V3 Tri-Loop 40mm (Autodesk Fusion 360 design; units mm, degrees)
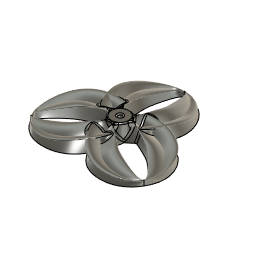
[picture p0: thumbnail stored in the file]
work_plane "WorkPlane9" AlongDistance 2
work_plane "WorkPlane10" AlongDistance -2
coil_primitive "CoilPrimitive4" Diameter 12 SectionSize 1 TaperAngle 0 Height 38.1 (= "( 25.4 * 1.5 ) * 1 mm")
coil_primitive "CoilPrimitive5" Diameter 25.4 SectionSize 1 TaperAngle 0 Height 38.1 (= "( 25.4 * 1.5 ) * 1 mm")
move "Move1"
sketch "Profile Start" plane through (2, 0, 0) normal (1, 0, 0) x axis (0, 1, 0)
  line L1 (-1.4, 0) -> (-2, 0)
  curve K1 (-2, 0) -> (-1.4, 0)
  curve K2 (-3, -1.5) -> (-1, 1.5)
  curve K3 (-0.4, 1.5) -> (-2.4, -1.5)
  curve K4 (1.75, 5) -> (2.25, 5)
  point P2 (-2, 0)
  point P4 (-1.4, 0)
  point P3 (2, 5)
  point P1 (0, 0)
  point P5 (-1, 1.5)
  point P8 (-0.4, 1.5)
  point P9 (2.25, 5)
  point P10 (1.75, 5)
  horizontal L1
  midpoint P2 K2
  midpoint P4 K3
  midpoint P3 K4
  dimension "d65" distance P1 P3 = 2
  dimension "d66" distance P1 P3 = 5
  dimension "d67" distance P1 P2 = 2
  dimension "d68" distance P2 P5 = 1
  dimension "d69" distance P2 P5 = 1.5
  dimension "d70" distance P4 P8 = 1.5
  dimension "d71" distance P5 P8 = 0.6
  dimension "d72" distance P9 P10 = 0.5
  dimension "d134" distance P2 P4 = 0.6
sketch "Profile End" plane through (-2, 0, 0) normal (1, 0, 0) x axis (0, 1, 0)
  curve K1 (3, 0) -> (2.2, 0)
  curve K2 (1.5, 1.5) -> (3.3167, -1.2219)
  curve K3 (-1.75, 4.2501) -> (-2.25, 4.2501)
  curve K4 (4, -1.5) -> (2, 1.5)
  line L1 (-1.75, 4.2501) -> (-2.25, 4.2501)
  line L2 (2.2, 0) -> (3, 0)
  point P5 (-1.75, 4.2501)
  point P9 (-2.25, 4.2501)
  point P4 (2.2, 0)
  point P8 (3, 0)
  point P6 (-2, 4.25)
  point P11 (0, 0)
  point P3 (1.5, 1.5)
  point P7 (2, 1.5)
  dimension "d84" distance P5 P9 = 0.5
  dimension "d89" distance P4 P8 = 0.8
  dimension "d101" distance P6 P11 = 4.25
  dimension "d102" distance P6 P11 = 2
  dimension "d103" distance P8 P11 = 3
  dimension "d104" distance P3 P11 = 1.5
  dimension "d105" distance P3 P11 = 1.5
  dimension "d106" distance P7 P11 = 2
  dimension "d107" distance P7 P11 = 1.5
sketch "Target Shape" plane through (0, 0, 0) normal (0, 0, 1) x axis (1, 0, 0)
  circle C1 centre (0, 0) radius 25.4
  circle C2 centre (0, 11.7) radius 13.7
  point P1 (0, 0)
  point P2 (0, 0)
  coincident P1 P2
  tangent C1 C2
  dimension "d95" diameter C1 = 50.8
sketch "Profile Edge" plane through (0, 0, 0) normal (1, 0, 0) x axis (0, 1, 0)
  line L1 (20, 0) -> (19.6, 0)
  curve K1 (19.6, 0) -> (20, 0)
  curve K2 (19.7001, 1.4961) -> (19.8999, 1.5039)
  curve K3 (20, 0.8) -> (20, -0.8)
  curve K4 (19.6, -0.8) -> (19.6, 0.8)
  point P4 (19.8, 1.5)
  point P3 (20, 0)
  point P2 (19.6, 0)
  point P1 (0, 0)
  point P5 (19.8999, 1.5039)
  point P6 (19.7001, 1.4961)
  horizontal L1
  midpoint P4 K2
  midpoint P3 K3
  midpoint P2 K4
  dimension "d96" distance P2 P3 = 0.4
  dimension "d98" distance P3 P4 = 1.5
  dimension "d121" distance P1 P4 = 1.5
  dimension "d138" distance P5 P6 = 0.2
  dimension "d196" distance P1 P3 = 20
  dimension "d209" distance P3 P4 = 0.2
work_plane "WorkPlane11" AlongDistance 10
sketch "Profile Mid" plane through (0, 10, 0) normal (0, 1, 0) x axis (1, 0, 0)
  line L1 (9.3, 0) -> (10, 0)
  curve K1 (9.3, 0) -> (10, 0)
  curve K2 (2.8905, -3.3974) -> (3.1095, -3.6026)
  curve K3 (11, 1.5) -> (7.6, -1.5)
  curve K4 (8.3, -1.5) -> (11.7, 1.5)
  line L2 (-3.7, 0) -> (-3, 0)
  curve K5 (-3.7, 0) -> (-3, 0)
  curve K6 (-4.915, -1.3314) -> (-1.085, 1.3314)
  curve K7 (-10.1189, -3.4086) -> (-9.8811, -3.5914)
  curve K8 (-1.5, 1.5) -> (-5.9, -1.5)
  point P3 (3, -3.5)
  point P4 (9.3, 0)
  point P2 (10, 0)
  point P15 (-10, -3.5)
  point P14 (-3.7, 0)
  point P11 (-3, 0)
  point P5 (3.1095, -3.6026)
  point P6 (2.8905, -3.3974)
  point P1 (0, 0)
  point P18 (-10.1189, -3.4086)
  point P19 (-9.8811, -3.5914)
  midpoint P3 K2
  midpoint P4 K3
  midpoint P2 K4
  midpoint P15 K7
  midpoint P14 K8
  midpoint P11 K6
  dimension "d109" distance P2 P4 = 0.7
  dimension "d110" distance P2 P3 = 3.5
  dimension "d111" distance P2 P3 = 7
  dimension "d112" distance P5 P6 = 0.3
  dimension "d113" distance P1 P2 = 10
  dimension "d117" distance P18 P19 = 0.3
  dimension "d118" distance P1 P15 = 10
  dimension "d187" distance P1 P15 = 3.5
  dimension "d197" distance P11 P14 = 0.7
  dimension "d198" distance P11 P15 = 7
sketch "Lower Rails" plane through (0, 0, 0) normal (0, 0, 1) x axis (1, 0, 0)
  curve K1 (-2, 2.2) -> (0, 20)
  curve K2 (-0.355, 2.2) -> (-3.645, 2.2)
  curve K3 (-3.9029, 5.1529) -> (-3.4971, 14.8471)
  curve K4 (-1.5, 20) -> (1.5, 20)
  curve K5 (-2, 3) -> (0, 19.6)
  curve K6 (-1.2, 3) -> (-2.8, 3)
  curve K7 (-2.9941, 6.3775) -> (-3.0059, 13.6225)
  curve K8 (-1.25, 19.6) -> (1.25, 19.6)
  curve K9 (0, 20) -> (2, -2)
  curve K10 (-3, 20) -> (3, 20)
  curve K11 (10, 12.7401) -> (10, 7.2599)
  curve K12 (2.5, -2) -> (1.5, -2)
  curve K13 (0, 19.6) -> (2, -1.4)
  curve K14 (-2.9656, 19.6) -> (2.9656, 19.6)
  curve K15 (9.3, 12.3) -> (9.3, 7.7)
  curve K16 (2.5, -1.4) -> (1.5, -1.4)
  circle C1 centre (0, 10) radius 10
  point P6 (-3.7, 10)
  point P9 (-3.7, 10)
  point P7 (-2, 2.2)
  point P10 (-2, 2.2)
  point P8 (0, 20)
  point P18 (-3, 10)
  point P20 (-3, 10)
  point P4 (-2, 3)
  point P19 (-2, 3)
  point P17 (0, 19.6)
  point P27 (0, 20)
  point P1 (0, 0)
  point P29 (2, -2)
  point P31 (2, -2)
  point P28 (10, 10)
  point P32 (10, 10)
  point P39 (2, -1.4)
  point P41 (2, -1.4)
  point P5 (9.3, 10)
  point P40 (9.3, 10)
  point P25 (1.25, 19.6)
  point P26 (-1.25, 19.6)
  point P15 (1.5, 20)
  point P16 (-1.5, 20)
  coincident P6 P9
  coincident P7 P10
  midpoint P10 K2
  midpoint P9 K3
  midpoint P8 K4
  coincident P18 P20
  coincident P4 P19
  midpoint P19 K6
  parallel K2 K6
  midpoint P18 K7
  midpoint P17 K8
  coincident P8 P27
  coincident P8 C1
  coincident P1 C1
  horizontal K4
  coincident P29 P31
  coincident P28 P32
  midpoint P8 K10
  horizontal K10
  midpoint P32 K11
  vertical K11
  midpoint P31 K12
  horizontal K12
  horizontal K6
  coincident P39 P41
  coincident P5 P40
  midpoint P17 K14
  horizontal K14
  midpoint P40 K15
  vertical K15
  midpoint P39 K16
  horizontal K16
  horizontal K8
  dimension "d136" distance P25 P26 = 2.5
  dimension "d137" distance P15 P16 = 3
work_plane "WorkPlane12" AlongDistance 5
sketch "Upper Rails" plane through (0, 0, 5) normal (0, 0, 1) x axis (1, 0, 0)
  line L1 (0, 20) -> (0, 19.6)
  curve K1 (2, 2) -> (0, 19.8)
  curve K2 (1.3, 2) -> (2.7, 2)
  curve K3 (3.01, 7.875) -> (2.9914, 12.125)
  curve K4 (1.5, 19.8) -> (-1.5, 19.8)
  curve K5 (-2, -2) -> (0, 19.8)
  curve K6 (1.5, -2) -> (-5.5, -2)
  curve K7 (-4, 19.8) -> (4, 19.8)
  curve K8 (-10.0007, 5.1189) -> (-10.0007, 14.8811)
  point P7 (2, 2)
  point P9 (2, 2)
  point P6 (3.0007, 10)
  point P5 (0, 19.8)
  point P18 (-2, -2)
  point P16 (0, 19.8)
  point P17 (-10.0007, 10)
  point P14 (-1.5, 19.8)
  point P15 (1.5, 19.8)
  coincident P7 P9
  midpoint P7 K2
  midpoint P6 K3
  midpoint P5 K4
  midpoint P18 K6
  midpoint P16 K7
  midpoint P17 K8
  dimension "d135" distance P14 P15 = 3
loft "Loft3" sketch "Profile Start" + "Profile Mid" + "Profile Edge" bodies "40mmx1x3 CCW"
loft "Loft4" sketch "Profile Edge" + "Profile Mid" + "Profile End"
circular_pattern "C-Pattern2" TotalAngle 360
combine "Combine2" bodies "Blade Template 2x1.6x3 (1)"
circular_pattern "C-Pattern3" TotalAngle 360
combine "Combine3"
fillet "Fillet2" radius 0.8
sketch "Hub" plane through (0, 0, 0) normal (0, 0, 1) x axis (1, 0, 0)
  circle C1 centre (0, 0) radius 3
  circle C2 centre (0, 0) radius 0.65
  point P1 (0, 0)
  point P2 (0, 0)
  coincident P1 P2
  concentric C1 C2
  dimension "d199" diameter C1 = 6
  dimension "d200" diameter C2 = 1.3
extrude "Extrude6" add sketch "Hub" along normal blind 6
fillet "Fillet7" radius 1
offset_faces "OffsetFaces12" distance -1
fillet "Fillet8" radius 0.35
chamfer "Chamfer7" distance 0.25
mirror "Mirror7" mirrorStitchTolerance 0.1 bodies "40mmx1x3 CW"
named bodies: "40mmx1x3 CCW", "Blade Template 2x1.6x3 (1)", "40mmx1x3 CW"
